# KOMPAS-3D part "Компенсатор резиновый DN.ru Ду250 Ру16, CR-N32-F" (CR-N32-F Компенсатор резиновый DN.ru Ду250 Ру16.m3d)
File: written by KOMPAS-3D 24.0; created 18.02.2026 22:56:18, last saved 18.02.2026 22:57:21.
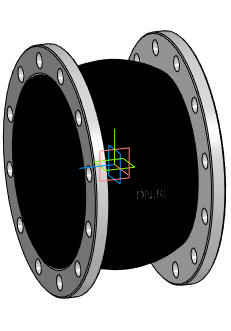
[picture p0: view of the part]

Document properties: Автор: DN.RU; Полное имя файла: D:\PROJECT CAD\DN.RU\...178(2)(ACTUALE). CR-N32-F Компенсатор резиновый DN.ru Ру10-16\CR-N32-F Компенсатор резиновый DN.ru Ру10-16\DN250_PN16\CR-N32-F Компенсатор резиновый DN.ru Ду250 Ру16.m3d

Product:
- Body: Твердое тело2  | qty 1
    Масса: 71.141217
- Part/product: Компенсатор резиновый DN.ru Ду250 Ру16  | designation CR-N32-F
    Масса: 25
    Раздел спецификации: Прочие изделия
    Комментарий: D140-02401
    Примечание: D140-02386
    additional columns: Типовые

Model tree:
1. Твердое тело2  (labels: Твердое тело2)

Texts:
  CR-N32-F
